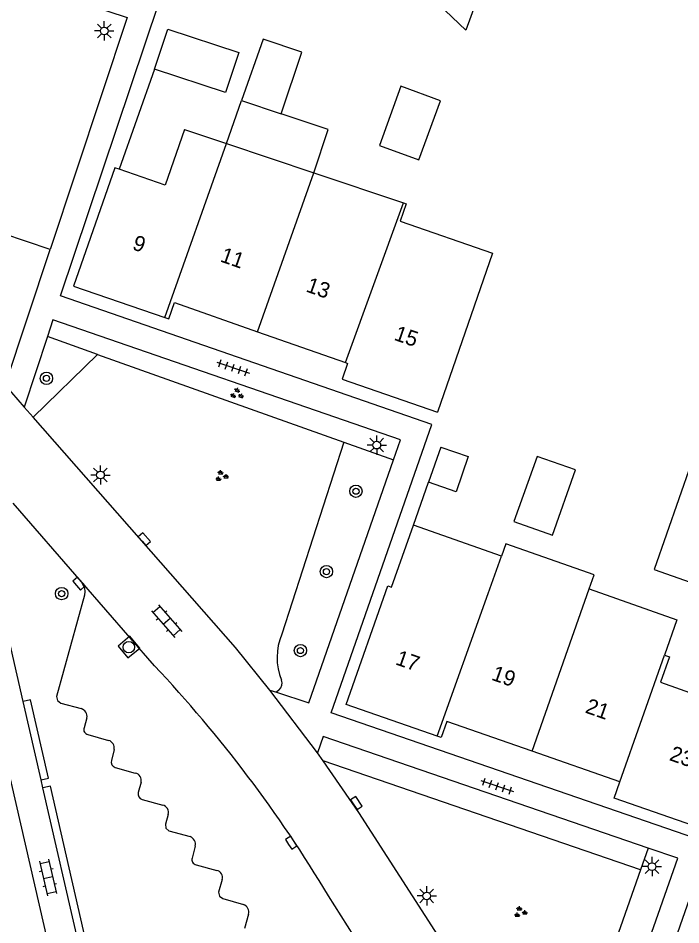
# Model space of a CAD drawing. Extents: x 136000 to 138005, y 398500 to 400500.
# Drawn here: x 137716.6 to 137759.7, y 398723.1 to 398782 of the extents above; entities that cross this region are included whole.
import ezdxf

# ---------------------------------------------------------------- set-up
doc = ezdxf.new("R2010")
doc.units = 0
for name, color, linetype in [('gg-afsc-muur', 7, 'Continuous'), ('gg-anno-huisnummerreeks BGT', 7, 'Continuous'), ('gg-bbg-bijgebouw', 7, 'Continuous'), ('gg-bbg-gedigitaliseerde bebouwing', 7, 'Continuous'), ('gg-bbg-gedigitaliseerde bijgebouw', 7, 'Continuous'), ('gg-bbg-hoofdgebouw', 7, 'Continuous'), ('gg-bbg-luifel en loopbrug', 7, 'Continuous'), ('gg-bbg-tussenscheiding', 7, 'Continuous'), ('gg-knt-verharding', 7, 'Continuous'), ('gg-knt-verharding nz', 7, 'Continuous'), ('gt-grn-groengrens', 7, 'Continuous'), ('gt-symb-boom', 7, 'Continuous'), ('gt-symb-groenvak', 7, 'Continuous'), ('gt-symb-klinker verharding', 7, 'Continuous'), ('gt-symb-kolk', 7, 'Continuous'), ('gt-symb-lichtmast', 7, 'Continuous'), ('gt-symb-rioolschacht', 7, 'Continuous'), ('gt-symb-tegel verharding', 7, 'Continuous')]:
    doc.layers.add(name, color=color, linetype=linetype)

# ---------------------------------------------------------------- blocks, each defined once
blk = doc.blocks.new('gt0-LMAST')
at = {"layer": 'gt-symb-lichtmast'}
for p, q in [((-0.005, 0.246), (-0.005, 0.621)), ((-0.182, 0.173), (-0.447, 0.438)), ((0.172, 0.173), (0.437, 0.438)), ((-0.255, -0.004), (-0.63, -0.004)), ((-0.182, -0.181), (-0.447, -0.446)), ((-0.005, -0.254), (-0.005, -0.629)), ((0.437, -0.446), (0.172, -0.181)), ((0.245, -0.004), (0.62, -0.004))]:
    blk.add_line(p, q, dxfattribs=at)
blk.add_circle((-0.005, -0.004), 0.25, dxfattribs=at)
blk = doc.blocks.new('gt0-GRVAK')
at = {"layer": 'gt-symb-groenvak'}
for p, q in [((-0.11, 0.189), (-0.228, 0.24)), ((-0.182, 0.153), (0.088, 0.153)), ((-0.091, 0.211), (-0.156, 0.322)), ((-0.047, 0.214), (-0.047, 0.393)), ((-0.004, 0.211), (0.061, 0.322)), ((0.015, 0.189), (0.133, 0.24)), ((0.262, -0.052), (0.197, 0.059)), ((0.305, -0.049), (0.305, 0.13)), ((0.349, -0.052), (0.414, 0.059)), ((-0.245, -0.228), (-0.363, -0.177)), ((-0.318, -0.264), (-0.047, -0.264)), ((-0.226, -0.206), (-0.291, -0.095)), ((-0.183, -0.203), (-0.183, -0.024)), ((-0.139, -0.206), (-0.074, -0.095)), ((-0.12, -0.228), (-0.002, -0.177)), ((0.243, -0.074), (0.125, -0.023)), ((0.17, -0.11), (0.441, -0.11)), ((0.368, -0.074), (0.486, -0.023))]:
    blk.add_line(p, q, dxfattribs=at)
blk = doc.blocks.new('gt0-BOOM')
at = {"layer": 'gt-symb-boom'}
for radius in [0.4, 0.2]:
    blk.add_circle((0, 0), radius, dxfattribs=at)
blk = doc.blocks.new('gt0-RS')
at = {"layer": 'gt-symb-rioolschacht'}
blk.add_lwpolyline([(-0.5, -0.5), (0.5, -0.5), (0.5, 0.5), (-0.5, 0.5)], close=True, dxfattribs=at)
blk.add_circle((0, 0), 0.375, dxfattribs=at)
blk = doc.blocks.new('gt0-KOLK')
at = {"layer": 'gt-symb-kolk'}
blk.add_lwpolyline([(0, 0), (0.375, 0), (0.375, 0.4), (-0.375, 0.4), (-0.375, 0), (0, 0)], dxfattribs=at)
blk = doc.blocks.new('gt0-KL1')
at = {"layer": 'gt-symb-klinker verharding'}
for p, q in [((-1.15, 0.3), (1.15, 0.3)), ((-1, -0.3), (-1, 0.3)), ((-0.5, 0.3), (-0.5, 0.45)), ((0, -0.3), (0, 0.3)), ((0.5, 0.3), (0.5, 0.45)), ((1, -0.3), (1, 0.3)), ((-1.15, -0.3), (1.15, -0.3)), ((-0.5, -0.45), (-0.5, -0.3)), ((0.5, -0.45), (0.5, -0.3))]:
    blk.add_line(p, q, dxfattribs=at)
blk = doc.blocks.new('gt0-TEG1')
at = {"layer": 'gt-symb-tegel verharding'}
for p, q in [((-1.125, 0), (1.125, 0)), ((-0.9, -0.25), (-0.9, 0.25)), ((-0.45, -0.25), (-0.45, 0.25)), ((0, -0.25), (0, 0.25)), ((0.45, -0.25), (0.45, 0.25)), ((0.9, -0.25), (0.9, 0.25))]:
    blk.add_line(p, q, dxfattribs=at)

msp = doc.modelspace()

# ---------------------------------------------------------------- linework, layer by layer
at = {"layer": 'gg-afsc-muur'}
for p, q in [((137725.496, 398778.7), (137723.193, 398772.205)), ((137742.296, 398749.101), (137743.284, 398751.883))]:
    msp.add_line(p, q, dxfattribs=at)
at = {"layer": 'gg-bbg-bijgebouw'}
for p, q in [((137725.496, 398778.7), (137726.349, 398781.3)), ((137744.081, 398754.165), (137743.284, 398751.883))]:
    msp.add_line(p, q, dxfattribs=at)
at = {"layer": 'gg-bbg-gedigitaliseerde bebouwing'}
for p, q in [((137727.44, 398774.78), (137730.158, 398773.87)), ((137730.158, 398773.87), (137735.825, 398771.972)), ((137735.825, 398771.972), (137741.648, 398770.022)), ((137748.022, 398747.087), (137742.296, 398749.101))]:
    msp.add_line(p, q, dxfattribs=at)
for points in [[(137741.648, 398770.022), (137741.841, 398769.957), (137741.451, 398768.825), (137747.425, 398766.762), (137743.86, 398756.44)], [(137753.707, 398744.95), (137754.029, 398745.866), (137748.305, 398747.878), (137748.022, 398747.087)], [(137753.707, 398744.95), (137759.413, 398742.944), (137758.609, 398740.655)], [(137758.609, 398740.655), (137758.924, 398740.545), (137758.345, 398738.891), (137760.889, 398738.001)]]:
    msp.add_lwpolyline(points, dxfattribs=at)
at = {"layer": 'gg-bbg-gedigitaliseerde bijgebouw'}
for points in [[(137747.812, 398786.995), (137745.715, 398781.223), (137742.547, 398784.251)], [(137726.349, 398781.3), (137730.961, 398779.787), (137730.108, 398777.187), (137725.496, 398778.7)], [(137740.09, 398773.739), (137742.659, 398772.806), (137744.056, 398776.653), (137741.487, 398777.586), (137740.09, 398773.739)], [(137744.081, 398754.165), (137745.865, 398753.542), (137745.067, 398751.26), (137743.284, 398751.883)], [(137748.823, 398749.325), (137751.334, 398748.448), (137752.817, 398752.693), (137750.337, 398753.56), (137748.823, 398749.325)], [(137762.691, 398752.273), (137760.332, 398753.097), (137757.928, 398746.217), (137760.275, 398745.397)]]:
    msp.add_lwpolyline(points, dxfattribs=at)
at = {"layer": 'gg-bbg-hoofdgebouw'}
for p, q in [((137732.183, 398761.648), (137737.883, 398759.652)), ((137743.844, 398735.402), (137737.94, 398737.45)), ((137755.71, 398732.42), (137750.005, 398734.417))]:
    msp.add_line(p, q, dxfattribs=at)
for points in [[(137727.44, 398774.78), (137726.18, 398771.16), (137723.193, 398772.205)], [(137723.193, 398772.205), (137722.92, 398772.3), (137720.23, 398764.61), (137726.166, 398762.567)], [(137726.166, 398762.567), (137726.42, 398762.48), (137726.78, 398763.54), (137732.183, 398761.648)], [(137737.883, 398759.652), (137738.03, 398759.6), (137737.67, 398758.58), (137743.86, 398756.44)], [(137737.94, 398737.45), (137740.63, 398745.15), (137740.885, 398745.061), (137742.296, 398749.101)], [(137750.005, 398734.417), (137744.48, 398736.35), (137744.11, 398735.31), (137743.844, 398735.402)], [(137761.51, 398729.22), (137755.34, 398731.37), (137755.71, 398732.42)]]:
    msp.add_lwpolyline(points, dxfattribs=at)
at = {"layer": 'gg-bbg-luifel en loopbrug'}
for p, q in [((137730.158, 398773.87), (137731.143, 398776.661)), ((137731.143, 398776.661), (137733.725, 398775.797))]:
    msp.add_line(p, q, dxfattribs=at)
for points in [[(137733.725, 398775.797), (137735.065, 398779.798), (137732.549, 398780.641), (137731.143, 398776.661)], [(137735.825, 398771.972), (137736.765, 398774.779), (137733.725, 398775.797)]]:
    msp.add_lwpolyline(points, dxfattribs=at)
at = {"layer": 'gg-bbg-tussenscheiding'}
for p, q in [((137726.166, 398762.567), (137730.158, 398773.87)), ((137732.183, 398761.648), (137735.825, 398771.972)), ((137737.883, 398759.652), (137741.648, 398770.022)), ((137747.153, 398744.655), (137748.022, 398747.087)), ((137752.324, 398741.015), (137753.707, 398744.95)), ((137743.844, 398735.402), (137747.153, 398744.655)), ((137750.005, 398734.417), (137752.324, 398741.015)), ((137755.71, 398732.42), (137758.609, 398740.655))]:
    msp.add_line(p, q, dxfattribs=at)
at = {"layer": 'gg-knt-verharding'}
for p, q in [((137715.784, 398758.18), (137718.715, 398766.996)), ((137718.534, 398761.34), (137717.036, 398756.754)), ((137715.784, 398758.18), (137717.036, 398756.754)), ((137717.036, 398756.754), (137717.603, 398756.109)), ((137720.74, 398745.423), (137716.31, 398750.52)), ((137716.962, 398737.641), (137714.126, 398750.025)), ((137722.26, 398705.937), (137712.345, 398749.119)), ((137736.073, 398734.306), (137732.989, 398738.386)), ((137732.989, 398738.386), (137733.405, 398738.249)), ((137718.124, 398732.564), (137716.962, 398737.641)), ((137721.1, 398736.58), (137720.92, 398735.94)), ((137721.17, 398735.51), (137722.51, 398735.12)), ((137722.87, 398734.53), (137722.69, 398733.82)), ((137736.437, 398733.785), (137736.073, 398734.306)), ((137722.94, 398733.37), (137724.24, 398733)), ((137718.246, 398732.032), (137718.124, 398732.564)), ((137723.91, 398707.3), (137718.246, 398732.032)), ((137724.62, 398732.41), (137724.44, 398731.74)), ((137724.69, 398731.29), (137726.03, 398730.92)), ((137728.14, 398728.26), (137727.929, 398727.48)), ((137728.19, 398727.05), (137729.53, 398726.68)), ((137731.59, 398723.83), (137731.34, 398722.91))]:
    msp.add_line(p, q, dxfattribs=at)
for points in [[(137761.274, 398728.544), (137736.96, 398736.9), (137743.49, 398755.64), (137719.38, 398763.98), (137725.79, 398783.06), (137701.316, 398791.144), (137699.778, 398796.748)], [(137721.145, 398782.9), (137723.72, 398782.05), (137718.715, 398766.996)], [(137741.004, 398753.325), (137741.46, 398754.63), (137718.89, 398762.43), (137718.534, 398761.34)], [(137732.989, 398738.386), (137730.74, 398741.16), (137717.603, 398756.109)], [(137733.405, 398738.249), (137735.5, 398737.56), (137741.004, 398753.325)], [(137720.74, 398745.423), (137720.951, 398745.012), (137720.974, 398744.78), (137720.94, 398744.55), (137719.12, 398737.97), (137719.182, 398737.701), (137719.4, 398737.53), (137720.73, 398737.18)], [(137718.124, 398732.564), (137718.612, 398732.676), (137717.449, 398737.752), (137716.962, 398737.641)], [(137757.543, 398728.128), (137736.44, 398735.37), (137736.073, 398734.306)], [(137750.803, 398711.092), (137749.641, 398713.313), (137748.38, 398715.48), (137738.766, 398730.448), (137736.437, 398733.785)], [(137724.413, 398707.345), (137718.734, 398732.144), (137718.246, 398732.032)], [(137726.38, 398730.31), (137726.2, 398729.69), (137726.233, 398729.423), (137726.43, 398729.24), (137727.8, 398728.87)], [(137751.474, 398710.849), (137753.38, 398710.16), (137759.46, 398727.47), (137757.543, 398728.128)], [(137778.523, 398701.452), (137754.92, 398709.63), (137761.017, 398727.113)], [(137729.88, 398726.08), (137729.65, 398725.27), (137729.704, 398725.008), (137729.92, 398724.85), (137731.27, 398724.46)]]:
    msp.add_lwpolyline(points, dxfattribs=at)
for centre, radius, start, end in [((137720.589, 398736.679), 0.521, 349.0714, 74.2501), ((137721.2, 398735.815), 0.307, 155.97388, 264.37316), ((137722.376, 398734.633), 0.505, 348.18087, 74.59967), ((137723.04, 398733.72), 0.364, 164.07914, 254.03007), ((137724.144, 398732.521), 0.489, 346.93293, 78.63563), ((137724.794, 398731.642), 0.368, 164.59697, 253.51224), ((137725.913, 398730.447), 0.487, 343.61939, 76.07247), ((137727.623, 398728.372), 0.529, 347.83023, 70.43835), ((137728.263, 398727.389), 0.347, 164.72787, 257.78569), ((137729.418, 398726.213), 0.481, 343.99689, 76.51599), ((137731.099, 398723.977), 0.512, 343.32486, 70.5305)]:
    msp.add_arc(centre, radius, start, end, dxfattribs=at)
at = {"layer": 'gg-knt-verharding nz'}
for p, q in [((137725.48, 398739.97), (137720.74, 398745.423)), ((137741.102, 398718.253), (137736.786, 398725.025))]:
    msp.add_line(p, q, dxfattribs=at)
msp.add_arc((137662.599, 398680.651), 86.445, 30.8852, 43.33034, dxfattribs=at)
at = {"layer": 'gt-grn-groengrens'}
for p, q in [((137718.715, 398766.996), (137715.633, 398768.021)), ((137721.785, 398760.18), (137718.534, 398761.34)), ((137717.603, 398756.109), (137721.785, 398760.18)), ((137721.785, 398760.18), (137737.778, 398754.476)), ((137737.778, 398754.476), (137733.751, 398742.02)), ((137737.778, 398754.476), (137741.004, 398753.325)), ((137733.585, 398738.41), (137733.405, 398738.249)), ((137757.045, 398726.712), (137736.437, 398733.785)), ((137757.543, 398728.128), (137757.045, 398726.712)), ((137757.045, 398726.712), (137751.474, 398710.849))]:
    msp.add_line(p, q, dxfattribs=at)
for centre, radius, start, end in [((137737.4, 398740.5), 3.953, 157.37933, 201.77669), ((137733.222, 398738.822), 0.549, 311.36085, 22.60962)]:
    msp.add_arc(centre, radius, start, end, dxfattribs=at)

# ---------------------------------------------------------------- block references
at = {"layer": 'gt-symb-boom'}
for p in [(137718.477, 398758.626), (137738.569, 398751.297), (137736.657, 398746.076), (137719.462, 398744.647), (137734.965, 398740.955)]:
    msp.add_blockref('gt0-BOOM', p, dxfattribs=at)
at = {"layer": 'gt-symb-groenvak', "rotation": -19.087244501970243}
msp.add_blockref('gt0-GRVAK', (137730.826, 398757.617), dxfattribs=at)
at = {"layer": 'gt-symb-groenvak'}
for p in [(137729.832, 398752.275), (137749.228, 398723.961)]:
    msp.add_blockref('gt0-GRVAK', p, dxfattribs=at)
at = {"layer": 'gt-symb-klinker verharding'}
for p, rotation in [((137726.274, 398742.862), -48.690081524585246), ((137718.581, 398726.224), -77.0611893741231)]:
    msp.add_blockref('gt0-KL1', p, dxfattribs=dict(at, rotation=rotation))
at = {"layer": 'gt-symb-kolk'}
for p, rotation in [((137724.687, 398748.049), -48.770950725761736), ((137720.435, 398745.167), -49.01346679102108), ((137738.432, 398730.942), -56.00796028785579), ((137734.197, 398728.367), -57.73964679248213)]:
    msp.add_blockref('gt0-KOLK', p, dxfattribs=dict(at, rotation=rotation))
at = {"layer": 'gt-symb-lichtmast'}
for p in [(137722.231, 398781.184), (137739.928, 398754.294), (137721.987, 398752.352), (137757.799, 398726.929), (137743.17, 398725.028)]:
    msp.add_blockref('gt0-LMAST', p, dxfattribs=at)
at = {"layer": 'gt-symb-rioolschacht', "rotation": 40.01095771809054}
msp.add_blockref('gt0-RS', (137723.827, 398741.176), dxfattribs=at)
at = {"layer": 'gt-symb-tegel verharding'}
for p, rotation in [((137730.593, 398759.319), -18.670583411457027), ((137747.735, 398732.152), -18.67058341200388)]:
    msp.add_blockref('gt0-TEG1', p, dxfattribs=dict(at, rotation=rotation))

# ---------------------------------------------------------------- texts
at = {"layer": 'gg-anno-huisnummerreeks BGT'}
for s, rotation, p in [('9', 341, (137723.992, 398767.016)), ('11', 340.7, (137729.698, 398766.227)), ('13', 340.7, (137735.268, 398764.277)), ('15', 340.9, (137740.985, 398761.137)), ('17', 340.9, (137741.078, 398740.066)), ('19', 340.7, (137747.31, 398739.068)), ('21', 340.7, (137753.399, 398736.937)), ('23', 340.8, (137758.861, 398733.85))]:
    msp.add_text(s, height=1, rotation=rotation, dxfattribs=at).set_placement(p)

doc.saveas('drawing.dxf')
